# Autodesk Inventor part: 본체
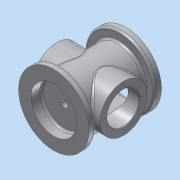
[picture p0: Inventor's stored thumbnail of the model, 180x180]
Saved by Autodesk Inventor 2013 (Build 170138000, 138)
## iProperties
Created: 2018-02
Part Number: 본체
Material: 알루미늄 6061
Document SubType Name: Modeling
Designer: dgall
Density: 2.71 g/cm^3
Mass: 771.845 g
Surface Area: 821.709 cm^2
Volume: 284.814 cm^3
Author: dgall
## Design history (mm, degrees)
sketch "스케치1"
  geometry: L1 (0, 54)-(0, -54); L2 (-52.5, 54)-(-37, 54); L3 (-37, 54)-(-37, 47); L4 (-37, 47)-(-33, 47); L5 (-34, -38)-(-34, -54); L6 (-34, -54)-(-52.5, -54); L7 (-52.5, -54)-(-52.5, -44); L8 (-52.5, -44)-(-38, -44); L9 (-38, -44)-(-38, 44); L10 (-38, 44)-(-52.5, 44); L11 (-52.5, 44)-(-52.5, 54); L12 (-34, -38)-(-5, -38); L13 (-5, -38)-(-5, -32); L14 (-33, 47)-(-33, -32); L15 (-33, -32)-(-5, -32); 2 further points
  constraints: 30 end point, 8 parallel, 5 perpendicular, 2 coincident, 2 horizontal alignment, 1 midpoint, 1 vertical
  dimensions: "d0" = 108 distance of L1.start L1.end; "d2" = 105 diameter of L11 L1; "d3" = 74 diameter of L3 L1; "d5" = 68 diameter of L5 L1; "d6" = 105 diameter of L7 L1; "d7" = 76 diameter of L9 L1; "d8" = 10 distance of L6.end L7.end; "d9" = 10 distance of L10.end L2.start; "d10" = 7 distance of L2.end L3.end; "d11" = 16 distance of L5.start L5.end; "d27" = 10 diameter of L13 L1; "d28" = 79 distance of L4.end L14.end; "d29" = 66 diameter of L14 L1
revolve "회전1" sketch "스케치1" stored, may be unused: angle "d12" = 90 deg
node "작업 평면1"
sketch "스케치2"
  geometry: C1 r 35 at (0, 0); C2 r 24 at (0, 0); 1 further point
  constraints: 2 centre point, 2 coincident
  dimensions: "d14" = 70 diameter of C1; "d15" = 48 diameter of C2
extrude "돌출1" join sketch "스케치2" stored distance "d16" = 10; taper "d17" = 0 deg
extrude "돌출2" cut sketch "스케치2" stored distance "d18" = 10; taper "d19" = 0 deg
node "작업 평면3"
sketch "스케치3"
  geometry: L1 (-7, 13)-(-7, -13); L2 (7, 13)-(7, -13); A1 r 7 centre (0, 13) between (7, 13) and (-7, 13); A2 r 7 centre (0, -13) between (-7, -13) and (7, -13); 2 further points
  constraints: 4 end point, 4 point on circle, 2 centre point, 2 tangent, 2 vertical, 2 vertical alignment, 1 horizontal alignment, 1 midpoint
  dimensions: "d21" = 7 radius of A1; "d22" = 7 radius of A2; "d24" = 40 dimension on A1 A2
extrude "돌출3" join sketch "스케치3" stored distance "d25" = 10; taper "d26" = 15 deg
fillet "모깎기1" dims "d30" = 3
sketch "스케치4" dims "d31" = 58
  geometry: C1 r 24 at (0, 0) reference; C2 r 35 at (0, 0) reference; 2 further points
  constraints: 2 vertical alignment, 1 coincident, 2 other
hole "구멍1" sketch "스케치4" at (0, 29) diameter "d32" = 3.242; stored, may be unused: countersink angle "d36" = 90 deg, drill point angle "d38" = 118 deg; dims "d33" = 4, "d34" = 4, "d35" = 2, "d37" = 6
node "작업 평면4"
sketch "스케치5" dims "d42" = 90
  geometry: C1 r 52.5 at (0, 0) reference; 3 further points
  constraints: 2 coincident, 2 vertical alignment, 2 other
hole "구멍2" sketch "스케치5" at (0, 45), (0, 0) diameter "d43" = 3.242; stored, may be unused: countersink angle "d47" = 90 deg, drill point angle "d49" = 118 deg; dims "d44" = 4, "d45" = 4, "d46" = 2, "d48" = 6
chamfer "모따기1" distance "d53" = 1; stored, may be unused: second distance "d54" = 2, angle "d55" = 45 deg
chamfer "모따기2" distance "d56" = 1; stored, may be unused: second distance "d57" = 2, angle "d58" = 45 deg
sketch "스케치6"
  geometry: A1 r 7 centre (0, 13) between (7, 13) and (-7, 13) reference; A2 r 7 centre (0, -13) between (-7, -13) and (7, -13) reference; 3 further points
  constraints: 2 coincident
hole "구멍3" sketch "스케치6" at (0, 13), (0, -13) diameter "d59" = 4.134; stored, may be unused: countersink angle "d63" = 90 deg, drill point angle "d65" = 118 deg; dims "d60" = 6, "d61" = 4, "d62" = 2, "d64" = 8
fillet "모깎기2" dims "d66" = 3
sketch "스케치7"
  geometry: C1 r 49.5 at (0, 0) reference; C2 r 43 at (0, 0)
  constraints: 1 centre point, 1 coincident, 1 other
  dimensions: "d67" = 86 diameter of C2
feature "엠보싱1" sketch "스케치7" dims "d0" = 108, "d2" = 105, "d3" = 74, "d5" = 68, "d6" = 105, "d7" = 76, "d8" = 10, "d9" = 10, "d10" = 7, "d11" = 16, "d18" = 10, "d27" = 10, "d28" = 79, "d29" = 66, "d68" = 0.5, "d69" = 0
node "솔리드1"
mirror "대칭1"
pattern_circular "원형 패턴1" dims angle "d40" = 360 deg
mirror "대칭2"
pattern_circular "원형 패턴2" dims angle "d51" = 360 deg
node "작업 평면2"
other parameters: "d20" = -55
